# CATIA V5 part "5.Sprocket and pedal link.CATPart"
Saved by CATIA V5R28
Part number: Sprocket and pedal link
Bounding box of the stored display mesh (mm): x -85.38 to 85.38, y -135 to 135, z -75.496 to 75.334
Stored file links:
  D:\Catia Cycle design\5.Sprocket and pedal link.CATPart
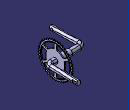
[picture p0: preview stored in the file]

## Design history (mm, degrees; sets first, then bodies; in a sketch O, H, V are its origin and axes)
Set1
  Sketch1 on yz-plane, origin (0, 0, 0), H (0, 1, 0), V (0, 0, 1)
    circle A1 centre (0, 0) radius 12.5
    radius A1 = 12.5
  Plane1: type Normal, Curve Sketch2, RefPoint Sketch2.P1, Ratio 0
  Plane2: type Normal, Curve Sketch2, RefPoint Sketch2.P4, Ratio 0
  Circle1: type CtrRad, Start 0, End 180, Center Sketch2.P1, Support Plane1, Radius 9, FirstDirection (-1, 0, 0)
  Circle2: type CtrRad, Start 0, End 180, Center Sketch2.P4, Support Plane2, Radius 9, FirstDirection (-1, 0, 0)
  Extremum1: Reference Circle1, Direction (1, 2, 3)
  Extremum2: Reference edge [end face of Pad1 | face of Pad1 from Sketch1.A1], Direction (1, 2, 3)
  Extremum3: Reference edge [face of Pad1 from Sketch1.A1 | start face of Pad1], Direction (1, 2, 3)
  Extremum4: Reference Circle2, Direction (1, 2, 3)
Body1 (main body)
  Pad1: profile Sketch1, direction (-1, 0, 0), length 20, mirrored extent
  Sketch2 on xy-plane, origin (0, 0, 0), H (1, 0, 0), V (0, 1, 0)
    point P1 (-75, -135)
    line L1 (-75, -135) -> (-75, -15)
    point P2 (-75, 0)
    line L2 (-60, 0) -> (60, 0)
    point P3 (75, 0)
    line L3 (75, 15) -> (75, 135)
    point P4 (75, 135)
    arc A1 centre (60, 15) radius 15 from (60, 0) to (75, 15) ccw
    arc A2 centre (-60, -15) radius 15 from (-75, -15) to (-60, 0) cw
    distance P2 P3 = 150
    distance P3 P4 = 135
    radius A1 = 15
    distance P1 P2 = 135
    radius A2 = 15
    coincidence: P2 H, L2 P3, L3 P3, L1 P2, L2 P2
    vertical: L1 V, L3 V
    horizontal: L2 H
    symmetry: P2 P3 V
    tangency: A1 L2, A1 L3, A2 L1, A2 L2
  Loft1: solid, Sections (Circle1; edge [end face of Pad1 | face of Pad1 from Sketch1.A1]), Spine Sketch2
  Loft2: solid, Sections (edge [face of Pad1 from Sketch1.A1 | start face of Pad1]; Circle2), Spine Sketch2
  Sketch3 on xy-plane, origin (0, 0, 0), H (1, 0, 0), V (0, 1, 0)
    line L1 (38.5, 34.5287) -> (42.5, 34.5287)
    line L2 (42.5, 34.5287) -> (42.5, -34.6431)
    line L3 (42.5, -34.6431) -> (38.5, -34.6431)
    line L4 (38.5, -34.6431) -> (38.5, 34.5287)
    distance V L4 = 38.5
    length L1 = 4
    horizontal: L1 H, L3 H
    vertical: L2 V, L4 V
  Pocket1: profile Sketch3, direction (0, 0, -1), length 42.5, mirrored extent
  Sketch4 on yz-plane, origin (0, 0, 0), H (0, 1, 0), V (0, 0, 1)
    circle A1 centre (-125, 0) radius 5
    point P1 (-125, 0)
    point P2 (-120, 0)
    reference projected line E1 (-135, 8.9999) -> (-135, -8.9999) from edge [face of Loft1 | face of Loft1]
    circle A2 centre (125, 0) radius 5
    radius A1 = 5
    distance P1 E1 = 10
    coincidence: P1 H, A1 P2, P2 H
    symmetry: A1 A2 V
  Pocket2: profile Sketch4, direction (-1, 0, 0), length 100, mirrored extent
  Sketch5 on xy-plane, origin (0, 0, 0), H (1, 0, 0), V (0, 1, 0)
    axis line L1 (75, 165.4714) -> (75, -152.0996)
    point P1 (75, 165.4714)
    point P2 (75, -152.0996)
    point P3 (-75, -152.0996)
    point P4 (-75, 165.4714)
    construction line L2 (-75, 165.4714) -> (-75, -152.0996)
    line L3 (82, 135) -> (99.1969, 135)
    line L4 (99.1969, 135) -> (99.1969, 115)
    line L5 (99.1969, 115) -> (82, 115)
    line L6 (82, 115) -> (82, 135)
    reference projected line E1 (66, 135) -> (84, 135) from edge [face of Loft2 | face of Loft2]
    line L7 (-91.5948, -115) -> (-82, -115)
    line L8 (-82, -115) -> (-82, -135)
    line L9 (-82, -135) -> (-91.5948, -135)
    line L10 (-91.5948, -135) -> (-91.5948, -115)
    reference projected line E2 (-84, -135) -> (-66, -135) from edge [face of Loft1 | face of Loft1]
    distance V L1 = 75
    distance L1 L6 = 7
    length L4 = 20
    distance L8 L2 = 7
    length L10 = 20
    vertical: L1 V, L4 V, L6 V, L8 V, L10 V
    symmetry: P2 P3 V, P1 P4 V, L1 L2 V
    horizontal: L3 H, L5 H, L7 H, L9 H
    coincidence: L3 E1, L9 E2
  Pocket3: profile Sketch5, direction (0, 0, -1), length 20, mirrored extent
  Sketch6 on face of Pocket1 from Sketch3.L4, origin (38.5, 0, 0), H (0, 1, 0), V (0, 0, 1)
    circle A1 centre (0, 0) radius 75.5
    radius A1 = 75.5
  Pad2: profile Sketch6, direction (1, 0, 0), length 4
  Sketch7 on end face of Pad2, origin (42.5, 0, 0), H (0, 1, 0), V (0, 0, 1)
    circle A1 centre (0, 75.5) radius 5
    point P1 (0, 75.5)
    reference projected circle E1 centre (0, 0) radius 75.5 from edge [face of Pad2 from Sketch6.A1 | end face of Pad2]
    radius A1 = 5
    coincidence: P1 V, P1 E1
  Pocket4: profile Sketch7, direction (-1, 0, 0), length 4
  CircPattern1: of Pocket4, instances 41, angular step 8.7805 {= 360.0*1 deg/CircPattern1.AngularNumber}, axis from X axis
  Sketch8 on end face of Pad2, origin (42.5, 0, 0), H (0, 1, 0), V (0, 0, 1)
    arc A1 centre (0, 0) radius 63 from (49.0695, 39.5119) to (10.8621, 62.0566) ccw
    point P1 (5, 62.8013)
    arc A2 centre (0, 0) radius 41.5 from (31.2951, 27.2555) to (8.9247, 40.529) ccw
    point P2 (33.8223, 24.048)
    line L1 (5, 45.412) -> (5, 57.1314)
    line L2 (37.5656, 26.2092) -> (47.6751, 32.0459)
    reference projected point E1 (-75.0877, 7.8791) from vertex [face of CircPattern1 | end face of Pad2 | face of Pad2 from Sketch6.A1]
    arc A3 centre (45.1751, 36.376) radius 5 from (49.0695, 39.5119) to (47.6751, 32.0459) cw
    arc A4 centre (35.0656, 30.5393) radius 5 from (31.2951, 27.2555) to (37.5656, 26.2092) ccw
    arc A5 centre (10, 45.412) radius 5 from (8.9247, 40.529) to (5, 45.412) cw
    arc A6 centre (10, 57.1314) radius 5 from (10.8621, 62.0566) to (5, 57.1314) ccw
    radius A1 = 63
    radius A2 = 41.5
    distance L1 V = 5
    distance P2 E1 H = 108.91
    angle L2 L1 = 60
    radius A3 = 5
    radius A4 = 5
    radius A5 = 5
    radius A6 = 5
    coincidence: L1 P1, A2 P2, L2 P2, A1 P1
    vertical: L1 V
    tangency: A3 A1, A3 L2, A4 A2, A4 L2, A5 A2, A5 L1, A6 A1, A6 L1
  Pocket5: profile Sketch8, direction (-1, 0, 0), length 4
  CircPattern2: of Pocket5, instances 6, angular step 60 {= 360.0*1 deg/CircPattern2.AngularNumber}, axis from X axis
  Sketch9 on end face of Pad2, origin (42.5, 0, 0), H (0, 1, 0), V (0, 0, 1)
    circle A1 centre (0, 0) radius 65
    circle A2 centre (0, 0) radius 75
    radius A1 = 65
    radius A2 = 75
  Pocket6: profile Sketch9, direction (-1, 0, 0), length 1
  Fillet1: radius 1, on edge [end face of Pocket6 | face of Pocket6 from Sketch9.A1]
  Sketch10 on xy-plane, origin (0, 0, 0), H (1, 0, 0), V (0, 1, 0)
